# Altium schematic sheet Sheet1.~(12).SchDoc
size A4
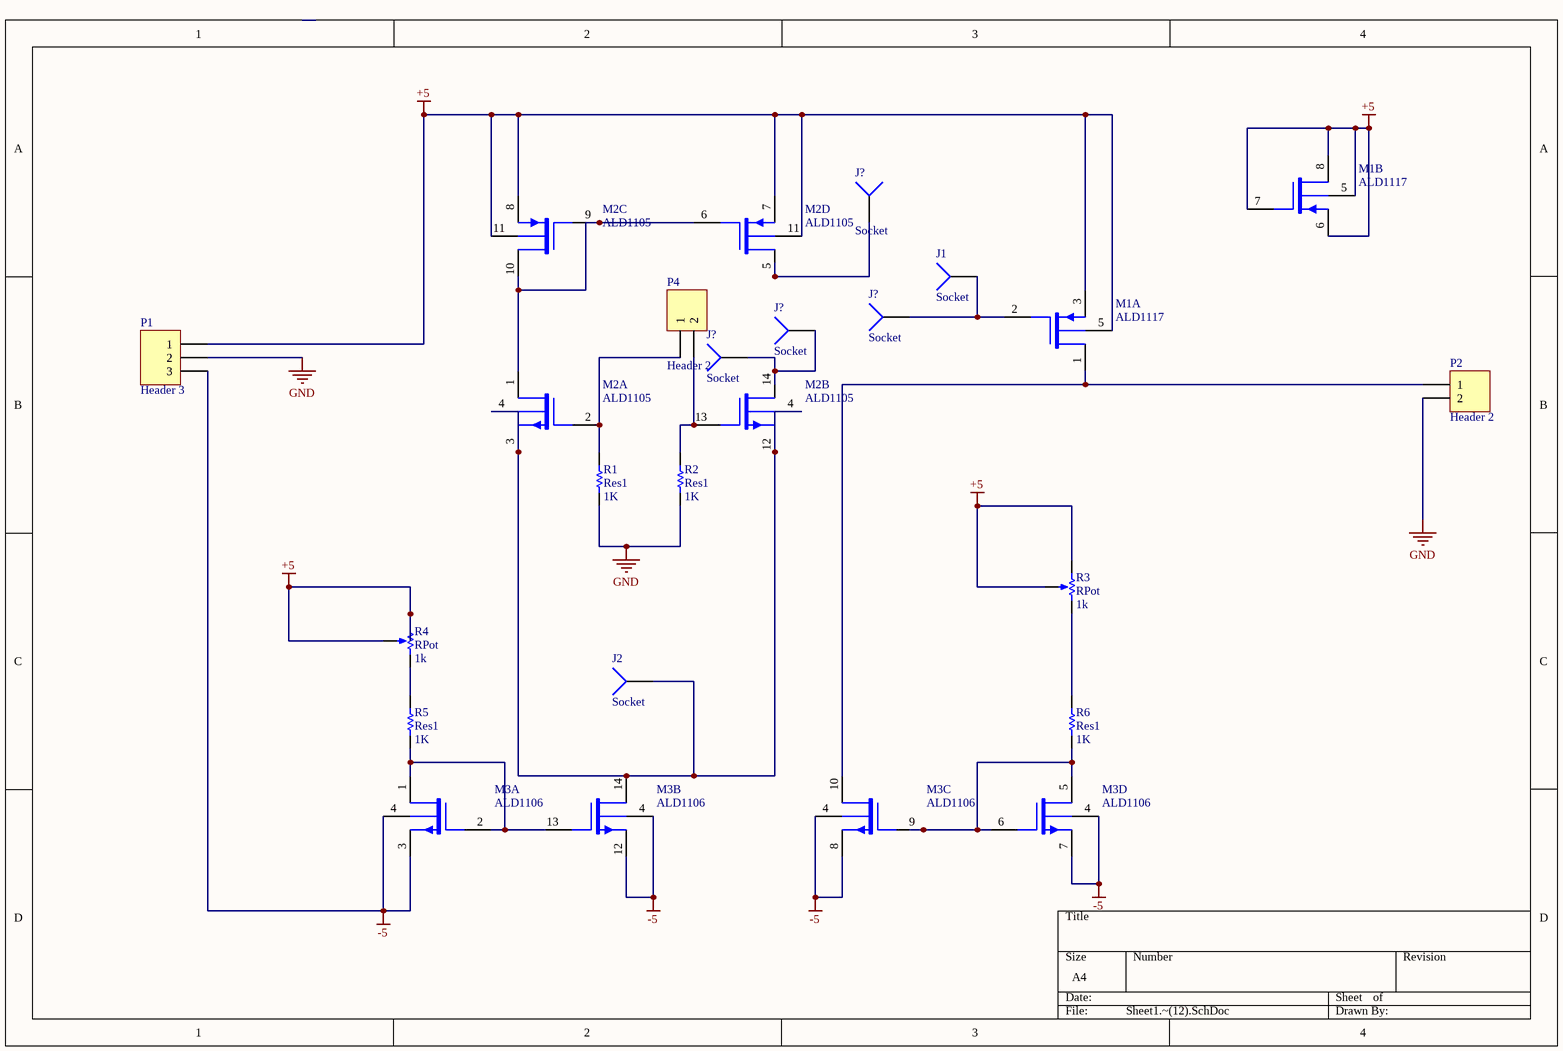
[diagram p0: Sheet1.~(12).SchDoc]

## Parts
(Parts that share a designator on the sheet are numbered #1, #2 ... from top to bottom, then left to right.)
J1  Socket  [PIN1]
J2  Socket  [PIN1]
J?#1  Socket  [PIN1]
J?#2  Socket  [PIN1]
J?#3  Socket  [PIN1]
J?#4  Socket  [PIN1]
M1  ALD1117  [DIP-8]  (parts A,B of 2)
M2  ALD1105  [DIP-14]  (parts A,B,C,D of 4)
M3  ALD1106  [DIP-14]  (parts A,B,C,D of 4)
P1  Header 3  [HDR1X3]
P2  Header 2  [HDR1X2]
P4  Header 2  [HDR1X2]
R1  Res1  value 1K  [AXIAL-0.3]
R2  Res1  value 1K  [AXIAL-0.3]
R3  RPot  value 1k  [VR5]
R4  RPot  value 1k  [VR5]
R5  Res1  value 1K  [AXIAL-0.3]
R6  Res1  value 1K  [AXIAL-0.3]

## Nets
+5: M1.3(SP1) M1.5(V+) M1.6(SP2) M1.7(GP2) M1.8(DP2) M2.7(SP1) M2.8(SP2) M2.11(V+) P1.1 R3.1(TOP) R3.2(TAP) R4.1(TOP) R4.2(TAP)
-5: M3.3(SN1) M3.4(V-) M3.7(SN4) M3.8(SN3) M3.12(SN2) P1.3
GND: P1.2 P2.2 R1.1 R2.1
NetJ1_1: J1.1 J?#2.1 M1.2(GP1)
NetJ2_1: J2.1 M2.3(SN1) M2.4(V-) M2.12(SN2) M3.14(DN2)
NetJ?#1_1: J?#1.1 M2.5(DP1)
NetJ?#3_1: J?#3.1 J?#4.1 M2.14(DN2)
NetM1_1: M1.1(DP1) M3.10(DN3) P2.1
NetM2_1: M2.1(DN1) M2.6(GP1) M2.9(GP2) M2.10(DP2)
NetM2_2: M2.2(GN1) P4.1 R1.2
NetM2_13: M2.13(GN2) P4.2 R2.2
NetM3_1: M3.1(DN1) M3.2(GN1) M3.13(GN2) R5.1
NetM3_5: M3.5(DN4) M3.6(GN4) M3.9(GN3) R6.1
NetR3_3: R3.3(BOT) R6.2
NetR4_3: R4.3(BOT) R5.2

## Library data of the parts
M1 = ALD1117: Dual P-channel matched MOSFET array
M2 = ALD1105: Dual P-channel and dual N-channel matched MOSFET array
M3 = ALD1106: Quad N-channel matched MOSFET array
P1 = Header 3: Header, 3-Pin
P2 P4 = Header 2: Header, 2-Pin
R1 R2 R5 R6 = Res1: Resistor
R3 R4 = RPot: Potentiometer; Sim Note: Enter the Resistance value and the set point into parameter fields.; Set Position: 0.5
